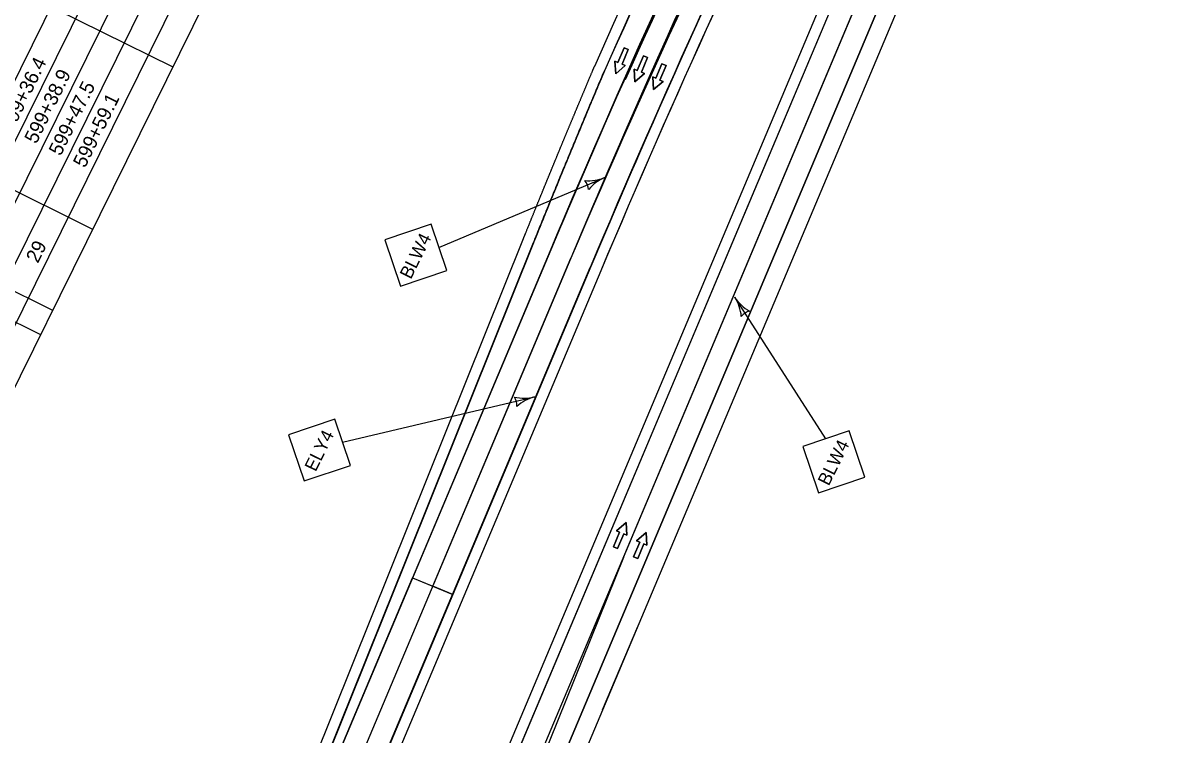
# Model space of a CAD drawing. Extents: x 14097936 to 14128734, y 8632000 to 8683104.
# Drawn here: x 14118361 to 14118997, y 8667745 to 8668139 of the extents above; entities that cross this region are included whole.
import ezdxf

# ---------------------------------------------------------------- set-up
doc = ezdxf.new("R2010")
doc.units = 0
for name, color, linetype in [('dsn_stg_shd_prev', 7, 'Continuous'), ('dsnPaintExistingBrokenLaneLineWhite', 7, 'Continuous'), ('dsnPaintExistingEdgeLineLeftYellow', 7, 'Continuous'), ('dsnPaintExistingEdgeLineRightWhite', 7, 'Continuous'), ('dsnPaintPlaceBrokenLaneWhite', 7, 'Continuous'), ('dsnPaintPlaceDottedLineWhite', 7, 'Continuous'), ('dsnPaintPlaceEdgeLineLeftYellow', 7, 'Continuous'), ('dsnPaintRemoveEdgeLineRightWhite', 7, 'Continuous'), ('dsnShadingGranular', 7, 'Continuous'), ('dsnShadingPaved', 7, 'Continuous'), ('dsnStdLabel', 7, 'Continuous'), ('dsnStgShadingPrevPav', 7, 'Continuous'), ('dsnTapeRemoveChannelizingLaneWhite', 7, 'Continuous'), ('dsnTapeRemoveEdgeLaneWhite', 7, 'Continuous'), ('dsnTapeRemoveEdgeLaneYellow', 7, 'Continuous'), ('Level 2', 7, 'Continuous'), ('Level 5', 7, 'Continuous')]:
    doc.layers.add(name, color=color, linetype=linetype)

msp = doc.modelspace()

# ---------------------------------------------------------------- linework, layer by layer
at = {"layer": 'dsn_stg_shd_prev'}
for p, q in [((14118497.16, 8667669.27), (14118637.96, 8668019.85)), ((14118652.65, 8668013.06), (14118415.89, 8667450.85)), ((14118652.65, 8668013.06), (14118415.89, 8667450.85)), ((14115815.77, 8661214.65), (14118674.76, 8668003.75)), ((14115815.77, 8661214.65), (14118674.76, 8668003.75)), ((14118680.66, 8668001.98), (14115821.67, 8661212.88))]:
    msp.add_line(p, q, dxfattribs=at)
for centre, radius, start, end in [((14123732.59, 8665873.82), 5512, 146.41866, 157.1633), ((14123732.96, 8665874.38), 5530, 150.3689, 156.09911), ((14123732.59, 8665873.82), 5512, 150.36196, 157.1633), ((14123733.72, 8665873.34), 5489.23, 150.6724, 157.1633), ((14123733.72, 8665873.34), 5489.23, 150.6724, 157.1633), ((14123732.96, 8665874.38), 5482, 150.67799, 157.1633)]:
    msp.add_arc(centre, radius, start, end, dxfattribs=at)
msp.add_open_spline([(14118637.96, 8668019.85), (14118638.32, 8668020.76), (14118639.58, 8668023.88), (14118641.88, 8668029.58), (14118643.7, 8668034.09), (14118645.66, 8668038.92), (14118647.59, 8668043.66), (14118649.53, 8668048.43), (14118651.47, 8668053.18), (14118653.42, 8668057.94), (14118655.38, 8668062.69), (14118657.33, 8668067.44), (14118659.29, 8668072.19), (14118661.26, 8668076.94), (14118663.23, 8668081.68), (14118665.21, 8668086.42), (14118667.19, 8668091.17), (14118669.16, 8668095.89), (14118671.18, 8668100.7), (14118673.07, 8668105.18), (14118675.45, 8668110.85), (14118676.77, 8668113.95), (14118677.15, 8668114.84)], degree=2, dxfattribs=at)
at = {"layer": 'dsnPaintExistingBrokenLaneLineWhite'}
msp.add_line((14118664.08, 8668008.96), (14118424.31, 8667439.59), dxfattribs=at)
at = {"layer": 'dsnPaintExistingEdgeLineLeftYellow'}
for p, q in [((14118759.37, 8668031.7), (14118817.06, 8668168.68)), ((14115900.95, 8661243.95), (14118759.37, 8668031.7)), ((14118675.14, 8668004.3), (14118435.37, 8667434.94))]:
    msp.add_line(p, q, dxfattribs=at)
msp.add_arc((14123732.96, 8665874.38), 5488, 152.69211, 157.1633, dxfattribs=at)
at = {"layer": 'dsnPaintExistingEdgeLineRightWhite'}
for p, q in [((14110924.38, 8649364.51), (14118874.68, 8668243.67)), ((14118643.53, 8668017.62), (14118412.94, 8667444.38))]:
    msp.add_line(p, q, dxfattribs=at)
for centre, radius, start, end in [((14123732.96, 8665874.38), 5524, 150.3689, 156.09858), ((14123767.91, 8665959.11), 5522.39, 157.04925, 158.11426)]:
    msp.add_arc(centre, radius, start, end, dxfattribs=at)
at = {"layer": 'dsnPaintPlaceBrokenLaneWhite'}
msp.add_line((14118537.63, 8667474.22), (14118951.74, 8668457.58), dxfattribs=at)
msp.add_arc((14123732.96, 8665874.38), 5500, 147.11705, 157.1633, dxfattribs=at)
at = {"layer": 'dsnPaintPlaceDottedLineWhite'}
msp.add_arc((14123732.96, 8665874.38), 5512, 154.51073, 156.09858, dxfattribs=at)
at = {"layer": 'dsnPaintPlaceEdgeLineLeftYellow'}
msp.add_line((14118675.14, 8668004.3), (14118598.82, 8667823.08), dxfattribs=at)
msp.add_arc((14123735.81, 8665873.06), 5491.14, 150.67353, 157.16217, dxfattribs=at)
at = {"layer": 'dsnPaintRemoveEdgeLineRightWhite'}
msp.add_lwpolyline([(14118693.19, 8667843.63), (14118809.62, 8668120.12), (14118926.06, 8668396.6)], dxfattribs=at)
msp.add_lwpolyline([(14118693.19, 8667843.63), (14118809.62, 8668120.12), (14118926.06, 8668396.6)], dxfattribs=at)
at = {"layer": 'dsnShadingGranular'}
msp.add_line((14118700.92, 8667805.29), (14118681.51, 8667759.2), dxfattribs=at)
at = {"layer": 'dsnShadingPaved'}
for p, q in [((14118937.12, 8668391.94), (14118374.42, 8667055.73)), ((14118352.3, 8667065.05), (14118824.82, 8668187.11)), ((14118413.25, 8667444.25), (14118643.53, 8668017.62)), ((14118653.02, 8668013.62), (14118576.7, 8667832.39)), ((14118653.02, 8668013.62), (14118576.7, 8667832.39)), ((14118587.76, 8667827.74), (14118664.08, 8668008.96)), ((14118587.76, 8667827.74), (14118664.08, 8668008.96)), ((14118675.14, 8668004.3), (14118598.82, 8667823.08)), ((14118413.25, 8667444.25), (14118576.7, 8667832.39)), ((14118576.7, 8667832.39), (14118534.18, 8667731.73)), ((14118576.7, 8667832.39), (14118587.76, 8667827.74)), ((14118576.7, 8667832.39), (14118598.82, 8667823.08)), ((14118598.82, 8667823.08), (14118587.76, 8667827.74)), ((14118598.82, 8667823.08), (14118435.37, 8667434.94))]:
    msp.add_line(p, q, dxfattribs=at)
for centre, radius, start, end in [((14123732.96, 8665874.38), 5500, 145.2497, 157.1633), ((14123732.96, 8665874.38), 5488, 145.2497, 157.1633), ((14123732.96, 8665874.38), 5500, 146.42378, 157.1633), ((14123655.03, 8665915.77), 5424.12, 146.80648, 157.24675), ((14123732.96, 8665874.38), 5524, 150.3689, 156.09858), ((14123732.96, 8665874.38), 5512, 150.3689, 157.1633)]:
    msp.add_arc(centre, radius, start, end, dxfattribs=at)
msp.add_open_spline([(14118643.53, 8668017.62), (14118644.16, 8668019.2), (14118645.44, 8668022.38), (14118647.36, 8668027.14), (14118649.28, 8668031.89), (14118651.21, 8668036.65), (14118653.15, 8668041.4), (14118655.08, 8668046.16), (14118657.03, 8668050.91), (14118658.97, 8668055.66), (14118660.92, 8668060.4), (14118662.88, 8668065.15), (14118664.84, 8668069.89), (14118666.8, 8668074.63), (14118668.77, 8668079.37), (14118670.74, 8668084.11), (14118672.72, 8668088.85), (14118674.7, 8668093.58), (14118676.69, 8668098.32), (14118678.68, 8668103.05), (14118680.67, 8668107.78), (14118682.01, 8668110.93), (14118682.67, 8668112.51)], degree=3, dxfattribs=at)
at = {"layer": 'dsnStdLabel'}
for p, q in [((14118220.06, 8668225.47), (14118444.17, 8668114.67)), ((14118204.08, 8667798.31), (14118410.17, 8668215.14)), ((14118217.53, 8667791.66), (14118423.62, 8668208.49)), ((14118230.97, 8667785.01), (14118437.07, 8668201.85)), ((14118244.42, 8667778.36), (14118450.51, 8668195.2)), ((14118257.87, 8667771.72), (14118463.96, 8668188.55)), ((14118175.74, 8668135.83), (14118399.84, 8668025.03)), ((14118153.58, 8668091.01), (14118377.68, 8667980.21)), ((14118146.93, 8668077.56), (14118371.04, 8667966.76)), ((14118591.21, 8668014.93), (14118682.87, 8668053.59)), ((14118805.07, 8667909.19), (14118754.76, 8667987.35)), ((14118537.98, 8667907.28), (14118644.05, 8667932.41))]:
    msp.add_line(p, q, dxfattribs=at)
for points in [[(14118047.21, 8667875.87), (14118253.3, 8668292.7), (14118477.41, 8668181.9), (14118271.31, 8667765.07)], [(14118569.96, 8667993.49), (14118595.53, 8668002.14), (14118586.88, 8668027.72), (14118561.3, 8668019.07)], [(14118516.73, 8667885.84), (14118542.31, 8667894.49), (14118533.66, 8667920.07), (14118508.08, 8667911.42)], [(14118800.94, 8667879.29), (14118826.51, 8667887.94), (14118817.86, 8667913.52), (14118792.29, 8667904.86)]]:
    msp.add_lwpolyline(points, close=True, dxfattribs=at)
for centre, radius, start, end in [((14118673.96, 8668074.73), 22.95, 264.79372, 292.86503), ((14118665.14, 8668046.11), 8.86, 5.1307, 40.59915), ((14118691.79, 8668032.44), 22.95, 112.86487, 140.93614), ((14118735.46, 8667974.93), 22.95, 4.69778, 32.76909), ((14118774.06, 8667999.77), 22.95, 212.76894, 240.8402), ((14118765.17, 8667971.17), 8.86, 105.03477, 140.50321), ((14118638.28, 8667954.58), 22.95, 256.63826, 284.70957), ((14118625.5, 8667927.49), 8.86, 356.97525, 32.4437), ((14118649.93, 8667910.18), 22.95, 104.70942, 132.78068)]:
    msp.add_arc(centre, radius, start, end, dxfattribs=at)
at = {"layer": 'dsnStgShadingPrevPav'}
for p, q in [((14115895.65, 8661246.83), (14118811.53, 8668171.01)), ((14118848.39, 8668155.49), (14115932.51, 8661231.3)), ((14118643.53, 8668017.62), (14118457.98, 8667555.62)), ((14118458.09, 8667555.57), (14118643.64, 8668017.57)), ((14118497.16, 8667669.27), (14118637.96, 8668019.85)), ((14118652.76, 8668013.01), (14118416.01, 8667450.8)), ((14118653.02, 8668013.62), (14118416.26, 8667451.41)), ((14115816.14, 8661215.2), (14118675.14, 8668004.3)), ((14115816.14, 8661215.2), (14118675.14, 8668004.3)), ((14118680.66, 8668001.98), (14115821.67, 8661212.88))]:
    msp.add_line(p, q, dxfattribs=at)
for centre, radius, start, end in [((14123732.96, 8665874.38), 5512, 146.41866, 157.1633), ((14123732.96, 8665874.38), 5530, 150.3689, 156.09911), ((14123732.96, 8665874.38), 5524, 150.3689, 156.09858), ((14123733.07, 8665874.33), 5524, 150.3689, 156.09858), ((14123732.7, 8665873.77), 5512, 150.36196, 157.1633), ((14123734.09, 8665873.9), 5489.23, 150.6724, 157.1633), ((14123732.96, 8665874.38), 5482, 150.67101, 157.1633), ((14123732.96, 8665874.38), 5488, 151.14296, 157.1633)]:
    msp.add_arc(centre, radius, start, end, dxfattribs=at)
for points, degree in [([(14118637.96, 8668019.85), (14118638.32, 8668020.76), (14118639.58, 8668023.88), (14118641.88, 8668029.58), (14118643.7, 8668034.09), (14118645.66, 8668038.92), (14118647.59, 8668043.66), (14118649.53, 8668048.43), (14118651.47, 8668053.18), (14118653.42, 8668057.94), (14118655.38, 8668062.69), (14118657.33, 8668067.44), (14118659.29, 8668072.19), (14118661.26, 8668076.94), (14118663.23, 8668081.68), (14118665.21, 8668086.42), (14118667.19, 8668091.17), (14118669.16, 8668095.89), (14118671.18, 8668100.7), (14118673.07, 8668105.18), (14118675.45, 8668110.85), (14118676.77, 8668113.95), (14118677.15, 8668114.84)], 2), ([(14118682.67, 8668112.51), (14118682.01, 8668110.93), (14118680.67, 8668107.78), (14118678.68, 8668103.05), (14118676.69, 8668098.32), (14118674.7, 8668093.58), (14118672.72, 8668088.85), (14118670.74, 8668084.11), (14118668.77, 8668079.37), (14118666.8, 8668074.63), (14118664.84, 8668069.89), (14118662.88, 8668065.15), (14118660.92, 8668060.4), (14118658.97, 8668055.66), (14118657.03, 8668050.91), (14118655.08, 8668046.16), (14118653.15, 8668041.4), (14118651.21, 8668036.65), (14118649.28, 8668031.89), (14118647.36, 8668027.14), (14118645.44, 8668022.38), (14118644.16, 8668019.2), (14118643.53, 8668017.62)], 3), ([(14118643.64, 8668017.57), (14118644.28, 8668019.15), (14118645.56, 8668022.33), (14118647.48, 8668027.09), (14118649.4, 8668031.84), (14118651.33, 8668036.6), (14118653.26, 8668041.35), (14118655.2, 8668046.11), (14118657.14, 8668050.86), (14118659.09, 8668055.61), (14118661.04, 8668060.35), (14118662.99, 8668065.1), (14118664.95, 8668069.84), (14118666.92, 8668074.59), (14118668.88, 8668079.33), (14118670.86, 8668084.06), (14118672.83, 8668088.8), (14118674.82, 8668093.54), (14118676.8, 8668098.27), (14118678.79, 8668103), (14118680.79, 8668107.73), (14118682.12, 8668110.88), (14118682.79, 8668112.46)], 3)]:
    msp.add_open_spline(points, degree=degree, dxfattribs=at)
at = {"layer": 'dsnTapeRemoveChannelizingLaneWhite'}
msp.add_line((14118693.19, 8667843.63), (14118405.41, 8667129.33), dxfattribs=at)
at = {"layer": 'dsnTapeRemoveEdgeLaneWhite'}
msp.add_arc((14123265.63, 8666052.94), 5012, 149.20104, 155.80033, dxfattribs=at)
msp.add_arc((14123265.63, 8666052.94), 5012, 149.20104, 155.80033, dxfattribs=at)
at = {"layer": 'dsnTapeRemoveEdgeLaneYellow'}
msp.add_arc((14123265.63, 8666052.94), 5000, 153.18219, 156.97073, dxfattribs=at)
at = {"layer": 'Level 2'}
for points in [[(14118695.88, 8668124.27), (14118693.58, 8668125.24), (14118690.18, 8668117.18), (14118688.46, 8668117.9), (14118688.91, 8668110.93), (14118694.22, 8668115.48), (14118692.49, 8668116.21)], [(14118706.53, 8668119.79), (14118704.22, 8668120.76), (14118700.83, 8668112.69), (14118699.1, 8668113.42), (14118699.56, 8668106.45), (14118704.86, 8668111), (14118703.13, 8668111.72)], [(14118716.78, 8668115.47), (14118714.47, 8668116.44), (14118711.08, 8668108.38), (14118709.35, 8668109.11), (14118709.8, 8668102.13), (14118715.11, 8668106.68), (14118713.38, 8668107.41)], [(14118687.64, 8667849.51), (14118689.95, 8667848.53), (14118693.36, 8667856.59), (14118695.08, 8667855.86), (14118694.64, 8667862.83), (14118689.33, 8667858.29), (14118691.06, 8667857.56)], [(14118698.76, 8667844.01), (14118701.07, 8667843.03), (14118704.48, 8667851.09), (14118706.2, 8667850.36), (14118705.76, 8667857.33), (14118700.45, 8667852.8), (14118702.18, 8667852.06)]]:
    msp.add_lwpolyline(points, close=True, dxfattribs=at)
at = {"layer": 'Level 5'}
for points in [[(14118692.49, 8668116.21), (14118694.22, 8668115.48), (14118688.91, 8668110.93), (14118688.46, 8668117.9), (14118690.18, 8668117.18), (14118693.58, 8668125.24), (14118695.88, 8668124.27), (14118692.49, 8668116.21)], [(14118703.13, 8668111.72), (14118704.86, 8668111), (14118699.56, 8668106.45), (14118699.1, 8668113.42), (14118700.83, 8668112.69), (14118704.22, 8668120.76), (14118706.53, 8668119.79), (14118703.13, 8668111.72)], [(14118713.38, 8668107.41), (14118715.11, 8668106.68), (14118709.8, 8668102.13), (14118709.35, 8668109.11), (14118711.08, 8668108.38), (14118714.47, 8668116.44), (14118716.78, 8668115.47), (14118713.38, 8668107.41)], [(14118691.06, 8667857.56), (14118689.33, 8667858.29), (14118694.64, 8667862.83), (14118695.08, 8667855.86), (14118693.36, 8667856.59), (14118689.95, 8667848.53), (14118687.64, 8667849.51), (14118691.06, 8667857.56)], [(14118702.18, 8667852.06), (14118700.45, 8667852.8), (14118705.76, 8667857.33), (14118706.2, 8667850.36), (14118704.48, 8667851.09), (14118701.07, 8667843.03), (14118698.76, 8667844.01), (14118702.18, 8667852.06)]]:
    msp.add_lwpolyline(points, dxfattribs=at)

# ---------------------------------------------------------------- texts
at = {"layer": 'dsnStdLabel'}
for s, height, p in [('599+36.4', 7.776, (14118355.25, 8668078.36)), ('599+38.9', 7.776, (14118368.7, 8668071.72)), ('599+47.5', 7.776, (14118382.14, 8668065.07)), ('599+59.1', 7.776, (14118395.59, 8668058.42)), ('29', 7.776, (14118369.58, 8668005.8)), ('BLW4', 7.2, (14118575.68, 8667996.95)), ('ELY4', 7.2, (14118523.08, 8667890.55)), ('BLW4', 7.2, (14118806.67, 8667882.75))]:
    msp.add_text(s, height=height, rotation=63.69117, dxfattribs=at).set_placement(p)

doc.saveas('drawing.dxf')
